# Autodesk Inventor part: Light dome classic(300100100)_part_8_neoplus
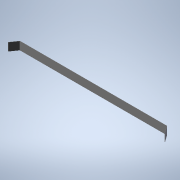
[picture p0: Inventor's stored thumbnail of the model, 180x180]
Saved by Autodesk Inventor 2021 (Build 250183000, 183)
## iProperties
Created: 2026-04
Part Number: Light dome classic(300100100)_part_8_neoplus
Material: Generic
Catalog Web Link: www.3dfindit.com
Description: Light dome classic_part_8_neoplus-
Vendor: KINGSPAN
Document SubType Name: Modeling
Designer: psAdmin
Manufacturer: KINGSPAN
Mass: 49.4652 g
Surface Area: 685.733 cm^2
Volume: 49.4652 cm^3
Density: 1 g/cm^3
Appearance: PSOLRGB-255-255-255
Category: PARTsolutions
Company: KINGSPAN
Title: Light dome classic(300100100)_part_8_neoplus
Author: Cadenas PARTsolutions
PSOL_IDENT_0: {$CADENAS_DATA/23d-libs/kingspan_kla/light_dome_classic_neoplus/parts/part_8.prj},268 {VTYP=3D},{NB=
PSOL_IDENT_1: Light dome classic(300100100)_part_8_neoplus},{LINA=Light dome classic(300100100)_part_8_neoplus},{N
PSOL_IDENT_2: N=Light dome classic_part_8_neoplus},{DATE=15.07.2024 10:56:16},{GEOMDATE=27.09.2022 13:43:52},{VERS
PSOL_IDENT_3: ION=},{LINEID=10},{WBVAR=LODLEVEL,L,W},{WBNUMERIC=W}  {NB=Light dome classic(300100100)_part_8_neopl
PSOL_IDENT_4: us},{LINA=Light dome classic(300100100)_part_8_neoplus},{KT=DUMMY},{IDNR=},{PN=Light dome classic},{
PSOL_IDENT_5: LODLEVEL=300},{L=100},{W=100},{WX=100,150,200,250,300},{LX=1000},{XWX=1000}
NB: Light dome classic(300100100)_part_8_neoplus
NN: Light dome classic_part_8_neoplus
NBSYN: $PN.($LODLEVEL.$L.$W.)_part_8_neoplus
LINA: Light dome classic(300100100)_part_8_neoplus
CATALOG: Light + Air
PN: Light dome classic
LODLEVEL: 300
L: 100
W: 100
SUPPLIER: KINGSPAN
ARTICLENO: Light dome classic(300100100)_part_8_neoplus
BOMINFO: Light dome classic(300100100)_part_8_neoplus
CREATOR: CADENAS GmbH
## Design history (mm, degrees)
sketch "Sketch_1"
  geometry: L1 (394.907, 293)-(393.076, 293); L2 (393.076, 293)-(369.096, 258.753); L3 (369.096, 258.753)-(-369.096, 258.753); L4 (-369.096, 258.753)-(-393.076, 293); L5 (-393.076, 293)-(-394.907, 293); L6 (-394.907, 293)-(-369.877, 257.253); L7 (-369.877, 257.253)-(369.877, 257.253); L8 (369.877, 257.253)-(394.907, 293)
  constraints: 16 end point
extrude "Extrusion1" join sketch "Sketch_1" stored distance "d0" = 40; taper "d1" = 0 deg
node "IP_8_XY"
node "IP_8_YZ"
node "IP_8_ZX"
node "IP_8_X"
node "IP_8_Y"
node "IP_8_Z"
node "IP_8_Center"
body "Solid1"
other parameters: "d2" = 0
